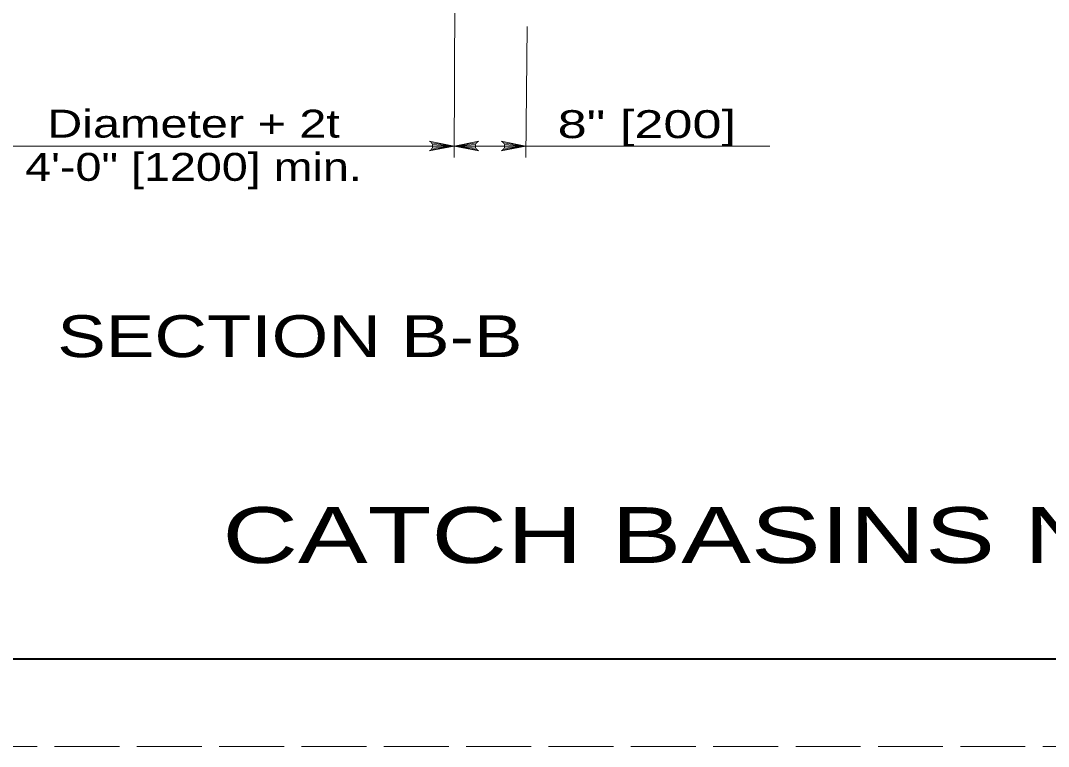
# Model space of a CAD drawing. Extents: x 1073.4 to 1107.4, y 719.4 to 741.4.
# Drawn here: x 1078.83 to 1084.72, y 719.35 to 723.51 of the extents above; entities that cross this region are included whole.
import ezdxf
from ezdxf.enums import TextEntityAlignment as Align

# ---------------------------------------------------------------- set-up
doc = ezdxf.new("R2010")
doc.units = 0
doc.header["$LTSCALE"] = 0.062
doc.linetypes.add('LONG_DASHED', pattern=[7.5, 6, -1.5])
doc.layers.add('1', color=7, linetype='Continuous', lineweight=13)

msp = doc.modelspace()

# ---------------------------------------------------------------- linework, layer by layer
at = {"layer": '1'}
for p, q in [((1081.3225, 723.97842), (1081.31533, 722.72683)), ((1081.73483, 723.47875), (1081.72758, 722.72683)), ((1081.18558, 722.77367), (1081.31533, 722.7935)), ((1081.18708, 722.8115), (1081.31533, 722.7935)), ((1081.1905, 722.782), (1081.31533, 722.7935)), ((1081.19142, 722.80258), (1081.31533, 722.7935)), ((1081.19275, 722.7935), (1081.31533, 722.7935)), ((1081.4435, 722.8115), (1081.31533, 722.7935)), ((1081.43917, 722.80258), (1081.31533, 722.7935)), ((1081.43783, 722.7935), (1081.31533, 722.7935)), ((1081.44008, 722.782), (1081.31533, 722.7935)), ((1081.445, 722.77367), (1081.31533, 722.7935)), ((1081.59783, 722.77367), (1081.72758, 722.7935)), ((1081.59942, 722.8115), (1081.72758, 722.7935)), ((1081.60275, 722.782), (1081.72758, 722.7935)), ((1081.60375, 722.80258), (1081.72758, 722.7935)), ((1081.60508, 722.7935), (1081.72758, 722.7935))]:
    msp.add_line(p, q, dxfattribs=at)
at = {"layer": '1', "linetype": 'LONG_DASHED'}
msp.add_lwpolyline([(1073.36142, 719.35408), (1107.36142, 719.35408), (1107.36142, 741.35408), (1073.36142, 741.35408)], close=True, dxfattribs=at)
at = {"layer": '1', "lineweight": 25}
msp.add_lwpolyline([(1106.86142, 719.85408), (1075.36142, 719.85408), (1075.36142, 740.85408)], dxfattribs=at)
at = {"layer": '1', "lineweight": 40}
msp.add_lwpolyline([(1075.36142, 740.85408), (1106.86142, 740.85408), (1106.86142, 719.85408), (1075.36142, 719.85408)], close=True, dxfattribs=at)
msp.add_lwpolyline([(1075.36142, 740.85408), (1106.86142, 740.85408), (1106.86142, 719.85408), (1075.36142, 719.85408)], close=True, dxfattribs=at)
at = {"layer": '1'}
for points in [[(1076.55733, 722.7935), (1078.32917, 722.7935), (1081.31533, 722.7935), (1083.12442, 722.7935)], [(1081.17375, 722.76517), (1081.31533, 722.7935), (1081.17375, 722.82183)], [(1081.45692, 722.76517), (1081.31533, 722.7935), (1081.45692, 722.82183)], [(1081.586, 722.76517), (1081.72758, 722.7935), (1081.586, 722.82183)]]:
    msp.add_lwpolyline(points, dxfattribs=at)
for centre, start, end in [((1081.16227, 722.79356), 292.08605, 67.91218), ((1081.46834, 722.79356), 112.08782, 247.91395), ((1081.57454, 722.79356), 292.08605, 67.91218)]:
    msp.add_arc(centre, 0.03056, start, end, dxfattribs=at)

# ---------------------------------------------------------------- texts
for s, width, p in [('Diameter + 2t', 1.3, (1079.82229, 722.84158)), ('4\'-0" [1200] min.', 1.25, (1079.82208, 722.59392))]:
    msp.add_text(s, height=0.16, dxfattribs=dict(at, width=width)).set_placement(p, align=Align.CENTER)
for s, height, width, p in [('8" [200]', 0.16, 1.4, (1081.90933, 722.83867)), ('SECTION B-B', 0.24, 1.3, (1079.0415, 721.58417)), ('CATCH BASINS No. 4A, No. 5A, and No. 8A', 0.32, 1.4, (1079.988, 720.40475))]:
    msp.add_text(s, height=height, dxfattribs=dict(at, width=width)).set_placement(p)

doc.saveas('drawing.dxf')
